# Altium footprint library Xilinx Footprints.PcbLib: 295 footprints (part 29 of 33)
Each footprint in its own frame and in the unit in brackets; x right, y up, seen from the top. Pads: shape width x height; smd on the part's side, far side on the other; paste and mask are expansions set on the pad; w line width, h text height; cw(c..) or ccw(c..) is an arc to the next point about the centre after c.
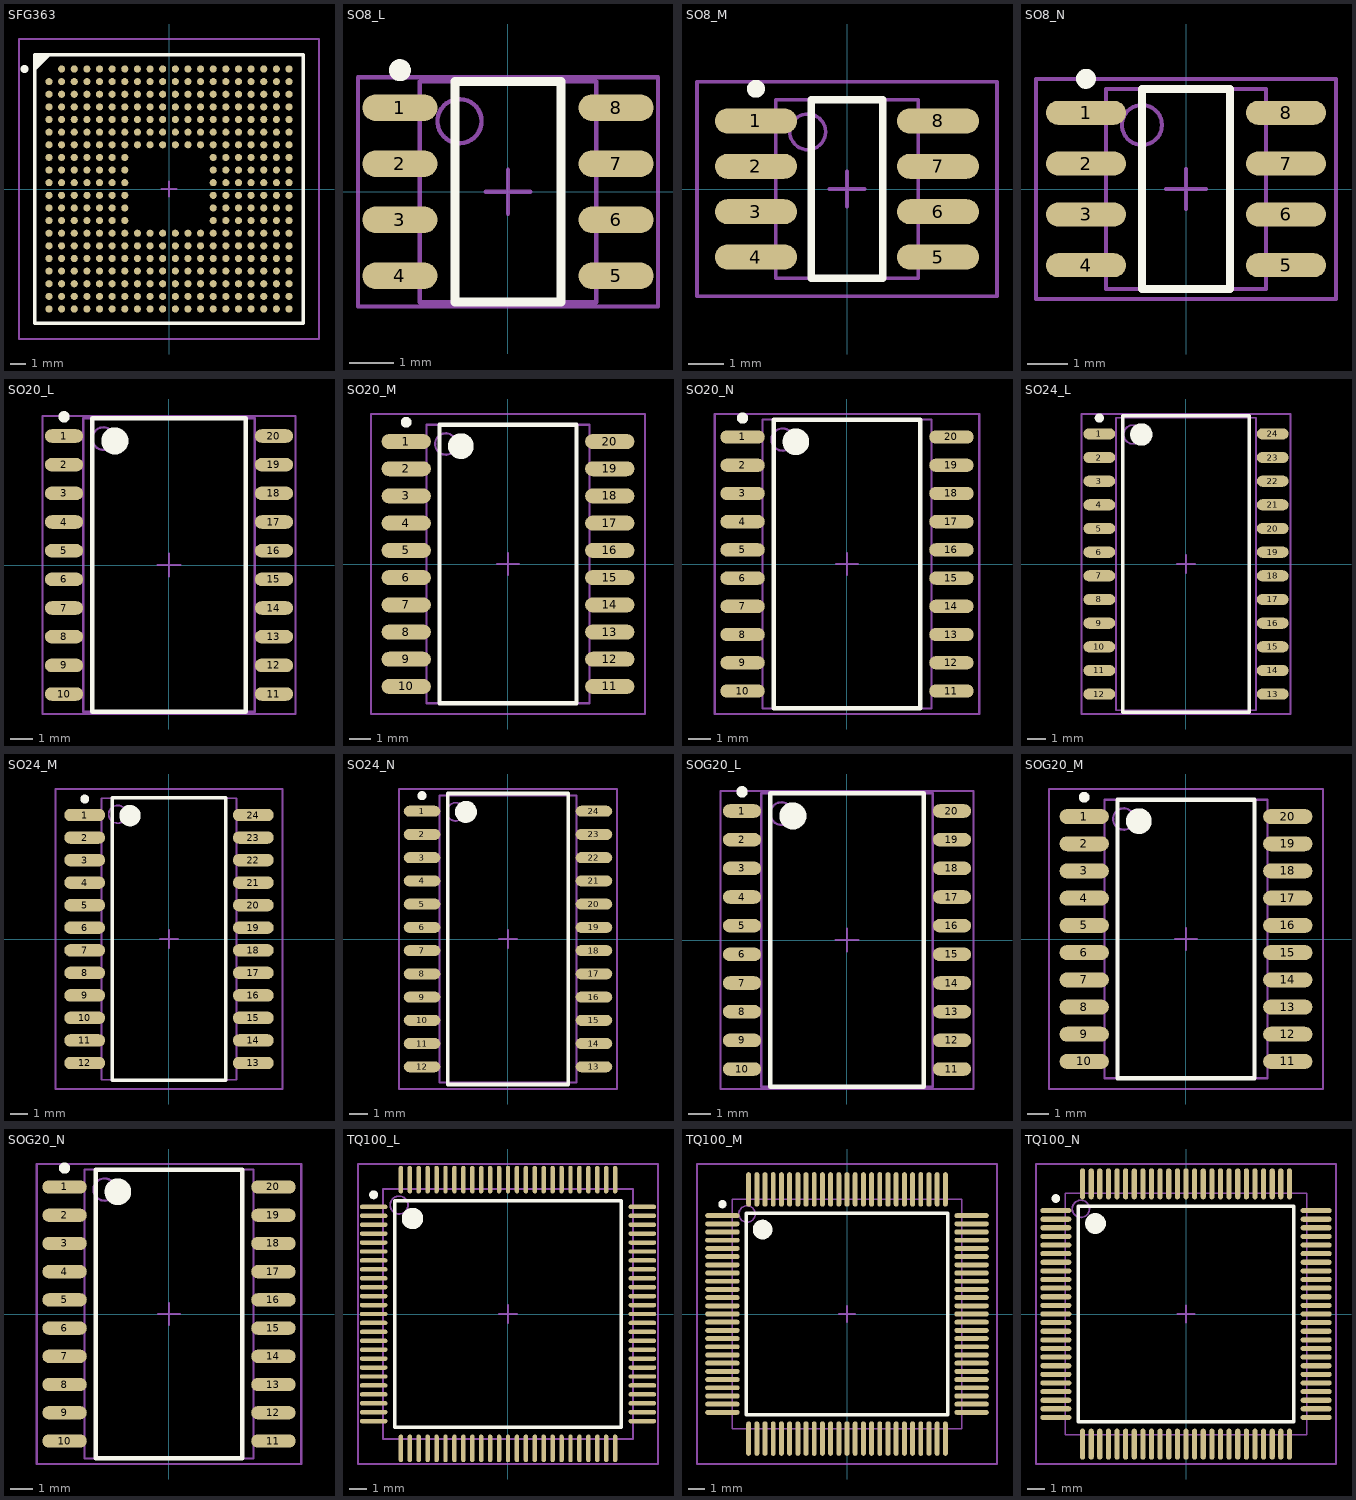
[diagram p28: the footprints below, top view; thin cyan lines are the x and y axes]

## SFG363 [mm] "363-Ball Flip Chip Fine Pitch Ball Grid Array (SFG363) - Pb-Free"
height 1.99
pads (363):
  round 0.45 smd: A2(-6.8,7.6) A3(-6,7.6) A4(-5.2,7.6) A5(-4.4,7.6) A6(-3.6,7.6) A7(-2.8,7.6) A8(-2,7.6) A9(-1.2,7.6) A10(-0.4,7.6) A11(0.4,7.6) A12(1.2,7.6) A13(2,7.6) A14(2.8,7.6) A15(3.6,7.6) A16(4.4,7.6) A17(5.2,7.6) A18(6,7.6) A19(6.8,7.6) A20(7.6,7.6) B1(-7.6,6.8) B2(-6.8,6.8) B3(-6,6.8) B4(-5.2,6.8) B5(-4.4,6.8) B6(-3.6,6.8) B7(-2.8,6.8) B8(-2,6.8) B9(-1.2,6.8) B10(-0.4,6.8) B11(0.4,6.8) B12(1.2,6.8) B13(2,6.8) B14(2.8,6.8) B15(3.6,6.8) B16(4.4,6.8) B17(5.2,6.8) B18(6,6.8) B19(6.8,6.8) B20(7.6,6.8) C1(-7.6,6) C2(-6.8,6) C3(-6,6) C4(-5.2,6) C5(-4.4,6) C6(-3.6,6) C7(-2.8,6) C8(-2,6) C9(-1.2,6) C10(-0.4,6) C11(0.4,6) C12(1.2,6) C13(2,6) C14(2.8,6) C15(3.6,6) C16(4.4,6) C17(5.2,6) C18(6,6) C19(6.8,6) C20(7.6,6) D1(-7.6,5.2) D2(-6.8,5.2) D3(-6,5.2) D4(-5.2,5.2) D5(-4.4,5.2) D6(-3.6,5.2) D7(-2.8,5.2) D8(-2,5.2) D9(-1.2,5.2) D10(-0.4,5.2) D11(0.4,5.2) D12(1.2,5.2) D13(2,5.2) D14(2.8,5.2) D15(3.6,5.2) D16(4.4,5.2) D17(5.2,5.2) D18(6,5.2) D19(6.8,5.2) D20(7.6,5.2) E1(-7.6,4.4) E2(-6.8,4.4) E3(-6,4.4) E4(-5.2,4.4) E5(-4.4,4.4) E6(-3.6,4.4) E7(-2.8,4.4) E8(-2,4.4) E9(-1.2,4.4) E10(-0.4,4.4) E11(0.4,4.4) E12(1.2,4.4) E13(2,4.4) E14(2.8,4.4) E15(3.6,4.4) E16(4.4,4.4) E17(5.2,4.4) E18(6,4.4) E19(6.8,4.4) E20(7.6,4.4) F1(-7.6,3.6) F2(-6.8,3.6) F3(-6,3.6) F4(-5.2,3.6) F5(-4.4,3.6) F6(-3.6,3.6) F7(-2.8,3.6) F8(-2,3.6) F9(-1.2,3.6) F10(-0.4,3.6) F11(0.4,3.6) F12(1.2,3.6) F13(2,3.6) F14(2.8,3.6) F15(3.6,3.6) F16(4.4,3.6) F17(5.2,3.6) F18(6,3.6) F19(6.8,3.6) F20(7.6,3.6) G1(-7.6,2.8) G2(-6.8,2.8) G3(-6,2.8) G4(-5.2,2.8) G5(-4.4,2.8) G6(-3.6,2.8) G7(-2.8,2.8) G8(-2,2.8) G9(-1.2,2.8) G10(-0.4,2.8) G11(0.4,2.8) G12(1.2,2.8) G13(2,2.8) G14(2.8,2.8) G15(3.6,2.8) G16(4.4,2.8) G17(5.2,2.8) G18(6,2.8) G19(6.8,2.8) G20(7.6,2.8) H1(-7.6,2) H2(-6.8,2) H3(-6,2) H4(-5.2,2) H5(-4.4,2) H6(-3.6,2) H7(-2.8,2) H14(2.8,2) H15(3.6,2) H16(4.4,2) H17(5.2,2) H18(6,2) H19(6.8,2) H20(7.6,2) J1(-7.6,1.2) J2(-6.8,1.2) J3(-6,1.2) J4(-5.2,1.2) J5(-4.4,1.2) J6(-3.6,1.2) J7(-2.8,1.2) J14(2.8,1.2) J15(3.6,1.2) J16(4.4,1.2) J17(5.2,1.2) J18(6,1.2) J19(6.8,1.2) J20(7.6,1.2) K1(-7.6,0.4) K2(-6.8,0.4) K3(-6,0.4) K4(-5.2,0.4) K5(-4.4,0.4) K6(-3.6,0.4) K7(-2.8,0.4) K14(2.8,0.4) K15(3.6,0.4) K16(4.4,0.4) K17(5.2,0.4) K18(6,0.4) K19(6.8,0.4) K20(7.6,0.4) L1(-7.6,-0.4) L2(-6.8,-0.4) L3(-6,-0.4) L4(-5.2,-0.4) L5(-4.4,-0.4) L6(-3.6,-0.4) L7(-2.8,-0.4) L14(2.8,-0.4) L15(3.6,-0.4) L16(4.4,-0.4) L17(5.2,-0.4) L18(6,-0.4) L19(6.8,-0.4) L20(7.6,-0.4) M1(-7.6,-1.2) M2(-6.8,-1.2) M3(-6,-1.2) M4(-5.2,-1.2) M5(-4.4,-1.2) M6(-3.6,-1.2) M7(-2.8,-1.2) M14(2.8,-1.2) M15(3.6,-1.2) M16(4.4,-1.2) M17(5.2,-1.2) M18(6,-1.2) M19(6.8,-1.2) M20(7.6,-1.2) N1(-7.6,-2) N2(-6.8,-2) N3(-6,-2) N4(-5.2,-2) N5(-4.4,-2) N6(-3.6,-2) N7(-2.8,-2) N14(2.8,-2) N15(3.6,-2) N16(4.4,-2) N17(5.2,-2) N18(6,-2) N19(6.8,-2) N20(7.6,-2) P1(-7.6,-2.8) P2(-6.8,-2.8) P3(-6,-2.8) P4(-5.2,-2.8) P5(-4.4,-2.8) P6(-3.6,-2.8) P7(-2.8,-2.8) P8(-2,-2.8) P9(-1.2,-2.8) P10(-0.4,-2.8) P11(0.4,-2.8) P12(1.2,-2.8) P13(2,-2.8) P14(2.8,-2.8) P15(3.6,-2.8) P16(4.4,-2.8) P17(5.2,-2.8) P18(6,-2.8) P19(6.8,-2.8) P20(7.6,-2.8) R1(-7.6,-3.6) R2(-6.8,-3.6) R3(-6,-3.6) R4(-5.2,-3.6) R5(-4.4,-3.6) R6(-3.6,-3.6) R7(-2.8,-3.6) R8(-2,-3.6) R9(-1.2,-3.6) R10(-0.4,-3.6) R11(0.4,-3.6) R12(1.2,-3.6) R13(2,-3.6) R14(2.8,-3.6) R15(3.6,-3.6) R16(4.4,-3.6) R17(5.2,-3.6) R18(6,-3.6) R19(6.8,-3.6) R20(7.6,-3.6) T1(-7.6,-4.4) T2(-6.8,-4.4) T3(-6,-4.4) T4(-5.2,-4.4) T5(-4.4,-4.4) T6(-3.6,-4.4) T7(-2.8,-4.4) T8(-2,-4.4) T9(-1.2,-4.4) T10(-0.4,-4.4) T11(0.4,-4.4) T12(1.2,-4.4) T13(2,-4.4) T14(2.8,-4.4) T15(3.6,-4.4) T16(4.4,-4.4) T17(5.2,-4.4) T18(6,-4.4) T19(6.8,-4.4) T20(7.6,-4.4) U1(-7.6,-5.2) U2(-6.8,-5.2) U3(-6,-5.2) U4(-5.2,-5.2) U5(-4.4,-5.2) U6(-3.6,-5.2) U7(-2.8,-5.2) U8(-2,-5.2) U9(-1.2,-5.2) U10(-0.4,-5.2) U11(0.4,-5.2) U12(1.2,-5.2) U13(2,-5.2) U14(2.8,-5.2) U15(3.6,-5.2) U16(4.4,-5.2) U17(5.2,-5.2) U18(6,-5.2) U19(6.8,-5.2) U20(7.6,-5.2) V1(-7.6,-6) V2(-6.8,-6) V3(-6,-6) V4(-5.2,-6) V5(-4.4,-6) V6(-3.6,-6) V7(-2.8,-6) V8(-2,-6) V9(-1.2,-6) V10(-0.4,-6) V11(0.4,-6) V12(1.2,-6) V13(2,-6) V14(2.8,-6) V15(3.6,-6) V16(4.4,-6) V17(5.2,-6) V18(6,-6) V19(6.8,-6) V20(7.6,-6) W1(-7.6,-6.8) W2(-6.8,-6.8) W3(-6,-6.8) W4(-5.2,-6.8) W5(-4.4,-6.8) W6(-3.6,-6.8) W7(-2.8,-6.8) W8(-2,-6.8) W9(-1.2,-6.8) W10(-0.4,-6.8) W11(0.4,-6.8) W12(1.2,-6.8) W13(2,-6.8) W14(2.8,-6.8) W15(3.6,-6.8) W16(4.4,-6.8) W17(5.2,-6.8) W18(6,-6.8) W19(6.8,-6.8) W20(7.6,-6.8) Y1(-7.6,-7.6) Y2(-6.8,-7.6) Y3(-6,-7.6) Y4(-5.2,-7.6) Y5(-4.4,-7.6) Y6(-3.6,-7.6) Y7(-2.8,-7.6) Y8(-2,-7.6) Y9(-1.2,-7.6) Y10(-0.4,-7.6) Y11(0.4,-7.6) Y12(1.2,-7.6) Y13(2,-7.6) Y14(2.8,-7.6) Y15(3.6,-7.6) Y16(4.4,-7.6) Y17(5.2,-7.6) Y18(6,-7.6) Y19(6.8,-7.6) Y20(7.6,-7.6)
Top Overlay:
  circle w0.25: c-9.15,7.6 r0.125
  region: -7.584,8.5 -8.5,7.584 -8.5,8.5
  lines w0.2: -8.5,7.584 -7.584,8.5 ; -8.5,-8.5 8.5,-8.5 8.5,8.5 -8.5,8.5 -8.5,-8.5
Mechanical 13:
  lines w0.1: -8.5,-8.5 8.5,-8.5 8.5,8.5 -8.5,8.5 -8.5,-8.5
Mechanical 15:
  lines w0.1: -0.5,0 0.5,0 ; 0,-0.5 0,0.5 ; -9.5,-9.5 9.5,-9.5 9.5,9.5 -9.5,9.5 -9.5,-9.5
3D body: height 1.99, standoff 0, extent -8.5,-8.5 8.5,8.5

## SO8_L [mm] "8-Pin Small Outline Package (SO8), IPC High Density"
height 1.73
pads (8):
  oval 1.7x0.6 smd: 1(-2.45,1.905) 2(-2.45,0.635) 3(-2.45,-0.635) 4(-2.45,-1.905) 5(2.45,-1.905) 6(2.45,-0.635) 7(2.45,0.635) 8(2.45,1.905)
Top Overlay:
  circle w0.25: c-2.45,2.755 r0.125
  lines w0.2: -1.2,-2.5 1.2,-2.5 1.2,2.5 -1.2,2.5 -1.2,-2.5
Mechanical 13:
  circle w0.1: c-1.1,1.6 r0.5
  lines w0.1: -2,-2.5 2,-2.5 2,2.5 -2,2.5 -2,-2.5
Mechanical 15:
  lines w0.1: -0.5,0 0.5,0 ; 0,-0.5 0,0.5 ; -3.4,-2.6 3.4,-2.6 3.4,2.6 -3.4,2.6 -3.4,-2.6
3D body: height 1.73, standoff 0, extent -2,-2.5 2,2.5

## SO8_M [mm] "8-Pin Small Outline Package (SO8), IPC Low Density"
height 1.73
pads (8):
  oval 2.3x0.7 smd: 1(-2.55,1.905) 2(-2.55,0.635) 3(-2.55,-0.635) 4(-2.55,-1.905) 5(2.55,-1.905) 6(2.55,-0.635) 7(2.55,0.635) 8(2.55,1.905)
Top Overlay:
  circle w0.25: c-2.55,2.805 r0.125
  lines w0.2: -1,-2.5 1,-2.5 1,2.5 -1,2.5 -1,-2.5
Mechanical 13:
  circle w0.1: c-1.1,1.6 r0.5
  lines w0.1: -2,-2.5 2,-2.5 2,2.5 -2,2.5 -2,-2.5
Mechanical 15:
  lines w0.1: -0.5,0 0.5,0 ; 0,-0.5 0,0.5 ; -4.2,-3 4.2,-3 4.2,3 -4.2,3 -4.2,-3
3D body: height 1.73, standoff 0, extent -2,-2.5 2,2.5

## SO8_N [mm] "8-Pin Small Outline Package (SO8), IPC Medium Density"
height 1.73
pads (8):
  oval 2x0.6 smd: 1(-2.5,1.905) 2(-2.5,0.635) 3(-2.5,-0.635) 4(-2.5,-1.905) 5(2.5,-1.905) 6(2.5,-0.635) 7(2.5,0.635) 8(2.5,1.905)
Top Overlay:
  circle w0.25: c-2.5,2.755 r0.125
  lines w0.2: -1.1,-2.5 1.1,-2.5 1.1,2.5 -1.1,2.5 -1.1,-2.5
Mechanical 13:
  circle w0.1: c-1.1,1.6 r0.5
  lines w0.1: -2,-2.5 2,-2.5 2,2.5 -2,2.5 -2,-2.5
Mechanical 15:
  lines w0.1: -0.5,0 0.5,0 ; 0,-0.5 0,0.5 ; -3.75,-2.75 3.75,-2.75 3.75,2.75 -3.75,2.75 -3.75,-2.75
3D body: height 1.73, standoff 0, extent -2,-2.5 2,2.5

## SO20_L [mm] "20-Pin Small Outline Package (SO20), IPC High Density"
height 2.65
pads (20):
  oval 1.7x0.6 smd: 1(-4.65,5.715) 2(-4.65,4.445) 3(-4.65,3.175) 4(-4.65,1.905) 5(-4.65,0.635) 6(-4.65,-0.635) 7(-4.65,-1.905) 8(-4.65,-3.175) 9(-4.65,-4.445) 10(-4.65,-5.715) 11(4.65,-5.715) 12(4.65,-4.445) 13(4.65,-3.175) 14(4.65,-1.905) 15(4.65,-0.635) 16(4.65,0.635) 17(4.65,1.905) 18(4.65,3.175) 19(4.65,4.445) 20(4.65,5.715)
Top Overlay:
  circle w0.25: c-4.65,6.565 r0.125
  circle w0.6: c-2.4,5.5 r0.3
  lines w0.2: -3.4,-6.5 -3.4,6.5 3.4,6.5 3.4,-6.5 -3.4,-6.5
Mechanical 13:
  circle w0.1: c-2.9,5.6 r0.5
  lines w0.1: -3.8,-6.5 -3.8,6.5 3.8,6.5 3.8,-6.5 -3.8,-6.5
Mechanical 15:
  lines w0.1: -0.5,0 0.5,0 ; 0,-0.5 0,0.5 ; -5.6,-6.6 -5.6,6.6 5.6,6.6 5.6,-6.6 -5.6,-6.6
3D body: height 2.65, standoff 0, extent -3.8,-6.5 3.8,6.5

## SO20_M [mm] "20-Pin Small Outline Package (SO20), IPC Low Density"
height 2.65
pads (20):
  oval 2.3x0.7 smd: 1(-4.75,5.715) 2(-4.75,4.445) 3(-4.75,3.175) 4(-4.75,1.905) 5(-4.75,0.635) 6(-4.75,-0.635) 7(-4.75,-1.905) 8(-4.75,-3.175) 9(-4.75,-4.445) 10(-4.75,-5.715) 11(4.75,-5.715) 12(4.75,-4.445) 13(4.75,-3.175) 14(4.75,-1.905) 15(4.75,-0.635) 16(4.75,0.635) 17(4.75,1.905) 18(4.75,3.175) 19(4.75,4.445) 20(4.75,5.715)
Top Overlay:
  circle w0.25: c-4.75,6.615 r0.125
  circle w0.6: c-2.2,5.5 r0.3
  lines w0.2: -3.2,-6.5 -3.2,6.5 3.2,6.5 3.2,-6.5 -3.2,-6.5
Mechanical 13:
  circle w0.1: c-2.9,5.6 r0.5
  lines w0.1: -3.8,-6.5 -3.8,6.5 3.8,6.5 3.8,-6.5 -3.8,-6.5
Mechanical 15:
  lines w0.1: -0.5,0 0.5,0 ; 0,-0.5 0,0.5 ; -6.4,-7 -6.4,7 6.4,7 6.4,-7 -6.4,-7
3D body: height 2.65, standoff 0, extent -3.8,-6.5 3.8,6.5

## SO20_N [mm] "20-Pin Small Outline Package (SO20), IPC Medium Density"
height 2.65
pads (20):
  oval 2x0.6 smd: 1(-4.7,5.715) 2(-4.7,4.445) 3(-4.7,3.175) 4(-4.7,1.905) 5(-4.7,0.635) 6(-4.7,-0.635) 7(-4.7,-1.905) 8(-4.7,-3.175) 9(-4.7,-4.445) 10(-4.7,-5.715) 11(4.7,-5.715) 12(4.7,-4.445) 13(4.7,-3.175) 14(4.7,-1.905) 15(4.7,-0.635) 16(4.7,0.635) 17(4.7,1.905) 18(4.7,3.175) 19(4.7,4.445) 20(4.7,5.715)
Top Overlay:
  circle w0.25: c-4.7,6.565 r0.125
  circle w0.6: c-2.3,5.5 r0.3
  lines w0.2: -3.3,-6.5 -3.3,6.5 3.3,6.5 3.3,-6.5 -3.3,-6.5
Mechanical 13:
  circle w0.1: c-2.9,5.6 r0.5
  lines w0.1: -3.8,-6.5 -3.8,6.5 3.8,6.5 3.8,-6.5 -3.8,-6.5
Mechanical 15:
  lines w0.1: -0.5,0 0.5,0 ; 0,-0.5 0,0.5 ; -5.95,-6.75 -5.95,6.75 5.95,6.75 5.95,-6.75 -5.95,-6.75
3D body: height 2.65, standoff 0, extent -3.8,-6.5 3.8,6.5

## SO24_L [mm] "24-Pin Small Outline Package (SO24), IPC High Density"
height 2.65
pads (24):
  oval 1.7x0.6 smd: 1(-4.65,6.985) 2(-4.65,5.715) 3(-4.65,4.445) 4(-4.65,3.175) 5(-4.65,1.905) 6(-4.65,0.635) 7(-4.65,-0.635) 8(-4.65,-1.905) 9(-4.65,-3.175) 10(-4.65,-4.445) 11(-4.65,-5.715) 12(-4.65,-6.985) 13(4.65,-6.985) 14(4.65,-5.715) 15(4.65,-4.445) 16(4.65,-3.175) 17(4.65,-1.905) 18(4.65,-0.635) 19(4.65,0.635) 20(4.65,1.905) 21(4.65,3.175) 22(4.65,4.445) 23(4.65,5.715) 24(4.65,6.985)
Top Overlay:
  circle w0.25: c-4.65,7.835 r0.125
  circle w0.6: c-2.4,6.95 r0.3
  lines w0.2: -3.4,-7.95 -3.4,7.95 3.4,7.95 3.4,-7.95 -3.4,-7.95
Mechanical 13:
  circle w0.1: c-2.85,6.95 r0.5
  lines w0.1: -3.75,-7.85 -3.75,7.85 3.75,7.85 3.75,-7.85 -3.75,-7.85
Mechanical 15:
  lines w0.1: -0.5,0 0.5,0 ; 0,-0.5 0,0.5 ; -5.6,-8.05 -5.6,8.05 5.6,8.05 5.6,-8.05 -5.6,-8.05
3D body: height 2.65, standoff 0, extent -3.75,-7.85 3.75,7.85

## SO24_M [mm] "24-Pin Small Outline Package (SO24), IPC Low Density"
height 2.65
pads (24):
  oval 2.3x0.7 smd: 1(-4.75,6.985) 2(-4.75,5.715) 3(-4.75,4.445) 4(-4.75,3.175) 5(-4.75,1.905) 6(-4.75,0.635) 7(-4.75,-0.635) 8(-4.75,-1.905) 9(-4.75,-3.175) 10(-4.75,-4.445) 11(-4.75,-5.715) 12(-4.75,-6.985) 13(4.75,-6.985) 14(4.75,-5.715) 15(4.75,-4.445) 16(4.75,-3.175) 17(4.75,-1.905) 18(4.75,-0.635) 19(4.75,0.635) 20(4.75,1.905) 21(4.75,3.175) 22(4.75,4.445) 23(4.75,5.715) 24(4.75,6.985)
Top Overlay:
  circle w0.25: c-4.75,7.885 r0.125
  circle w0.6: c-2.2,6.95 r0.3
  lines w0.2: -3.2,-7.95 -3.2,7.95 3.2,7.95 3.2,-7.95 -3.2,-7.95
Mechanical 13:
  circle w0.1: c-2.9,7.025 r0.5
  lines w0.1: -3.8,-7.925 -3.8,7.925 3.8,7.925 3.8,-7.925 -3.8,-7.925
Mechanical 15:
  lines w0.1: -0.5,0 0.5,0 ; 0,-0.5 0,0.5 ; -6.4,-8.45 -6.4,8.45 6.4,8.45 6.4,-8.45 -6.4,-8.45
3D body: height 2.65, standoff 0, extent -3.8,-7.925 3.8,7.925

## SO24_N [mm] "24-Pin Small Outline Package (SO24), IPC Medium Density"
height 2.65
pads (24):
  oval 2x0.6 smd: 1(-4.7,6.985) 2(-4.7,5.715) 3(-4.7,4.445) 4(-4.7,3.175) 5(-4.7,1.905) 6(-4.7,0.635) 7(-4.7,-0.635) 8(-4.7,-1.905) 9(-4.7,-3.175) 10(-4.7,-4.445) 11(-4.7,-5.715) 12(-4.7,-6.985) 13(4.7,-6.985) 14(4.7,-5.715) 15(4.7,-4.445) 16(4.7,-3.175) 17(4.7,-1.905) 18(4.7,-0.635) 19(4.7,0.635) 20(4.7,1.905) 21(4.7,3.175) 22(4.7,4.445) 23(4.7,5.715) 24(4.7,6.985)
Top Overlay:
  circle w0.25: c-4.7,7.835 r0.125
  circle w0.6: c-2.3,6.95 r0.3
  lines w0.2: -3.3,-7.95 -3.3,7.95 3.3,7.95 3.3,-7.95 -3.3,-7.95
Mechanical 13:
  circle w0.1: c-2.85,6.95 r0.5
  lines w0.1: -3.75,-7.85 -3.75,7.85 3.75,7.85 3.75,-7.85 -3.75,-7.85
Mechanical 15:
  lines w0.1: -0.5,0 0.5,0 ; 0,-0.5 0,0.5 ; -5.95,-8.2 -5.95,8.2 5.95,8.2 5.95,-8.2 -5.95,-8.2
3D body: height 2.65, standoff 0, extent -3.75,-7.85 3.75,7.85

## SOG20_L [mm] "20-Pin Small Outline Package (SOG20) - Pb-Free, IPC High Density"
height 2.65
pads (20):
  oval 1.7x0.6 smd: 1(-4.65,5.715) 2(-4.65,4.445) 3(-4.65,3.175) 4(-4.65,1.905) 5(-4.65,0.635) 6(-4.65,-0.635) 7(-4.65,-1.905) 8(-4.65,-3.175) 9(-4.65,-4.445) 10(-4.65,-5.715) 11(4.65,-5.715) 12(4.65,-4.445) 13(4.65,-3.175) 14(4.65,-1.905) 15(4.65,-0.635) 16(4.65,0.635) 17(4.65,1.905) 18(4.65,3.175) 19(4.65,4.445) 20(4.65,5.715)
Top Overlay:
  circle w0.25: c-4.65,6.565 r0.125
  circle w0.6: c-2.4,5.5 r0.3
  lines w0.2: -3.4,-6.5 -3.4,6.5 3.4,6.5 3.4,-6.5 -3.4,-6.5
Mechanical 13:
  circle w0.1: c-2.9,5.6 r0.5
  lines w0.1: -3.8,-6.5 -3.8,6.5 3.8,6.5 3.8,-6.5 -3.8,-6.5
Mechanical 15:
  lines w0.1: -0.5,0 0.5,0 ; 0,-0.5 0,0.5 ; -5.6,-6.6 -5.6,6.6 5.6,6.6 5.6,-6.6 -5.6,-6.6
3D body: height 2.65, standoff 0, extent -3.8,-6.5 3.8,6.5

## SOG20_M [mm] "20-Pin Small Outline Package (SOG20) - Pb-Free, IPC Low Density"
height 2.65
pads (20):
  oval 2.3x0.7 smd: 1(-4.75,5.715) 2(-4.75,4.445) 3(-4.75,3.175) 4(-4.75,1.905) 5(-4.75,0.635) 6(-4.75,-0.635) 7(-4.75,-1.905) 8(-4.75,-3.175) 9(-4.75,-4.445) 10(-4.75,-5.715) 11(4.75,-5.715) 12(4.75,-4.445) 13(4.75,-3.175) 14(4.75,-1.905) 15(4.75,-0.635) 16(4.75,0.635) 17(4.75,1.905) 18(4.75,3.175) 19(4.75,4.445) 20(4.75,5.715)
Top Overlay:
  circle w0.25: c-4.75,6.615 r0.125
  circle w0.6: c-2.2,5.5 r0.3
  lines w0.2: -3.2,-6.5 -3.2,6.5 3.2,6.5 3.2,-6.5 -3.2,-6.5
Mechanical 13:
  circle w0.1: c-2.9,5.6 r0.5
  lines w0.1: -3.8,-6.5 -3.8,6.5 3.8,6.5 3.8,-6.5 -3.8,-6.5
Mechanical 15:
  lines w0.1: -0.5,0 0.5,0 ; 0,-0.5 0,0.5 ; -6.4,-7 -6.4,7 6.4,7 6.4,-7 -6.4,-7
3D body: height 2.65, standoff 0, extent -3.8,-6.5 3.8,6.5

## SOG20_N [mm] "20-Pin Small Outline Package (SOG20) - Pb-Free, IPC Medium Density"
height 2.65
pads (20):
  oval 2x0.6 smd: 1(-4.7,5.715) 2(-4.7,4.445) 3(-4.7,3.175) 4(-4.7,1.905) 5(-4.7,0.635) 6(-4.7,-0.635) 7(-4.7,-1.905) 8(-4.7,-3.175) 9(-4.7,-4.445) 10(-4.7,-5.715) 11(4.7,-5.715) 12(4.7,-4.445) 13(4.7,-3.175) 14(4.7,-1.905) 15(4.7,-0.635) 16(4.7,0.635) 17(4.7,1.905) 18(4.7,3.175) 19(4.7,4.445) 20(4.7,5.715)
Top Overlay:
  circle w0.25: c-4.7,6.565 r0.125
  circle w0.6: c-2.3,5.5 r0.3
  lines w0.2: -3.3,-6.5 -3.3,6.5 3.3,6.5 3.3,-6.5 -3.3,-6.5
Mechanical 13:
  circle w0.1: c-2.9,5.6 r0.5
  lines w0.1: -3.8,-6.5 -3.8,6.5 3.8,6.5 3.8,-6.5 -3.8,-6.5
Mechanical 15:
  lines w0.1: -0.5,0 0.5,0 ; 0,-0.5 0,0.5 ; -5.95,-6.75 -5.95,6.75 5.95,6.75 5.95,-6.75 -5.95,-6.75
3D body: height 2.65, standoff 0, extent -3.8,-6.5 3.8,6.5

## TQ100_L [mm] "100-Pin Thin Quad Flat Pack (TQ100), IPC High Density"
height 1.6
pads (100):
  oval 1.55x0.25 smd: 1(-7.525,6) 2(-7.525,5.5) 3(-7.525,5) 4(-7.525,4.5) 5(-7.525,4) 6(-7.525,3.5) 7(-7.525,3) 8(-7.525,2.5) 9(-7.525,2) 10(-7.525,1.5) 11(-7.525,1) 12(-7.525,0.5) 13(-7.525,0) 14(-7.525,-0.5) 15(-7.525,-1) 16(-7.525,-1.5) 17(-7.525,-2) 18(-7.525,-2.5) 19(-7.525,-3) 20(-7.525,-3.5) 21(-7.525,-4) 22(-7.525,-4.5) 23(-7.525,-5) 24(-7.525,-5.5) 25(-7.525,-6) 51(7.525,-6) 52(7.525,-5.5) 53(7.525,-5) 54(7.525,-4.5) 55(7.525,-4) 56(7.525,-3.5) 57(7.525,-3) 58(7.525,-2.5) 59(7.525,-2) 60(7.525,-1.5) 61(7.525,-1) 62(7.525,-0.5) 63(7.525,0) 64(7.525,0.5) 65(7.525,1) 66(7.525,1.5) 67(7.525,2) 68(7.525,2.5) 69(7.525,3) 70(7.525,3.5) 71(7.525,4) 72(7.525,4.5) 73(7.525,5) 74(7.525,5.5) 75(7.525,6)
  oval 0.25x1.55 smd: 26(-6,-7.525) 27(-5.5,-7.525) 28(-5,-7.525) 29(-4.5,-7.525) 30(-4,-7.525) 31(-3.5,-7.525) 32(-3,-7.525) 33(-2.5,-7.525) 34(-2,-7.525) 35(-1.5,-7.525) 36(-1,-7.525) 37(-0.5,-7.525) 38(0,-7.525) 39(0.5,-7.525) 40(1,-7.525) 41(1.5,-7.525) 42(2,-7.525) 43(2.5,-7.525) 44(3,-7.525) 45(3.5,-7.525) 46(4,-7.525) 47(4.5,-7.525) 48(5,-7.525) 49(5.5,-7.525) 50(6,-7.525) 76(6,7.525) 77(5.5,7.525) 78(5,7.525) 79(4.5,7.525) 80(4,7.525) 81(3.5,7.525) 82(3,7.525) 83(2.5,7.525) 84(2,7.525) 85(1.5,7.525) 86(1,7.525) 87(0.5,7.525) 88(0,7.525) 89(-0.5,7.525) 90(-1,7.525) 91(-1.5,7.525) 92(-2,7.525) 93(-2.5,7.525) 94(-3,7.525) 95(-3.5,7.525) 96(-4,7.525) 97(-4.5,7.525) 98(-5,7.525) 99(-5.5,7.525) 100(-6,7.525)
Top Overlay:
  circle w0.25: c-7.525,6.675 r0.125
  circle w0.6: c-5.35,5.35 r0.3
  lines w0.2: -6.35,-6.35 -6.35,6.35 6.35,6.35 6.35,-6.35 -6.35,-6.35
Mechanical 13:
  circle w0.1: c-6.1,6.1 r0.5
  lines w0.1: -7,-7 -7,7 7,7 7,-7 -7,-7
Mechanical 15:
  lines w0.1: -0.5,0 0.5,0 ; 0,-0.5 0,0.5 ; -8.4,-8.4 -8.4,8.4 8.4,8.4 8.4,-8.4 -8.4,-8.4
3D body: height 1.6, standoff 0, extent -7,-7 7,7

## TQ100_M [mm] "100-Pin Thin Quad Flat Pack (TQ100), IPC Low Density"
height 1.6
pads (100):
  oval 2.1x0.3 smd: 1(-7.6,6) 2(-7.6,5.5) 3(-7.6,5) 4(-7.6,4.5) 5(-7.6,4) 6(-7.6,3.5) 7(-7.6,3) 8(-7.6,2.5) 9(-7.6,2) 10(-7.6,1.5) 11(-7.6,1) 12(-7.6,0.5) 13(-7.6,0) 14(-7.6,-0.5) 15(-7.6,-1) 16(-7.6,-1.5) 17(-7.6,-2) 18(-7.6,-2.5) 19(-7.6,-3) 20(-7.6,-3.5) 21(-7.6,-4) 22(-7.6,-4.5) 23(-7.6,-5) 24(-7.6,-5.5) 25(-7.6,-6) 51(7.6,-6) 52(7.6,-5.5) 53(7.6,-5) 54(7.6,-4.5) 55(7.6,-4) 56(7.6,-3.5) 57(7.6,-3) 58(7.6,-2.5) 59(7.6,-2) 60(7.6,-1.5) 61(7.6,-1) 62(7.6,-0.5) 63(7.6,0) 64(7.6,0.5) 65(7.6,1) 66(7.6,1.5) 67(7.6,2) 68(7.6,2.5) 69(7.6,3) 70(7.6,3.5) 71(7.6,4) 72(7.6,4.5) 73(7.6,5) 74(7.6,5.5) 75(7.6,6)
  oval 0.3x2.1 smd: 26(-6,-7.6) 27(-5.5,-7.6) 28(-5,-7.6) 29(-4.5,-7.6) 30(-4,-7.6) 31(-3.5,-7.6) 32(-3,-7.6) 33(-2.5,-7.6) 34(-2,-7.6) 35(-1.5,-7.6) 36(-1,-7.6) 37(-0.5,-7.6) 38(0,-7.6) 39(0.5,-7.6) 40(1,-7.6) 41(1.5,-7.6) 42(2,-7.6) 43(2.5,-7.6) 44(3,-7.6) 45(3.5,-7.6) 46(4,-7.6) 47(4.5,-7.6) 48(5,-7.6) 49(5.5,-7.6) 50(6,-7.6) 76(6,7.6) 77(5.5,7.6) 78(5,7.6) 79(4.5,7.6) 80(4,7.6) 81(3.5,7.6) 82(3,7.6) 83(2.5,7.6) 84(2,7.6) 85(1.5,7.6) 86(1,7.6) 87(0.5,7.6) 88(0,7.6) 89(-0.5,7.6) 90(-1,7.6) 91(-1.5,7.6) 92(-2,7.6) 93(-2.5,7.6) 94(-3,7.6) 95(-3.5,7.6) 96(-4,7.6) 97(-4.5,7.6) 98(-5,7.6) 99(-5.5,7.6) 100(-6,7.6)
Top Overlay:
  circle w0.6: c-5.15,5.15 r0.3
  circle w0.25: c-7.6,6.7 r0.125
  lines w0.2: -6.15,-6.15 6.15,-6.15 6.15,6.15 -6.15,6.15 -6.15,-6.15
Mechanical 13:
  circle w0.1: c-6.1,6.1 r0.5
  lines w0.1: -7,-7 7,-7 7,7 -7,7 -7,-7
Mechanical 15:
  lines w0.1: -0.5,0 0.5,0 ; 0,-0.5 0,0.5 ; -9.15,-9.15 9.15,-9.15 9.15,9.15 -9.15,9.15 -9.15,-9.15
3D body: height 1.6, standoff 0, extent -7,-7 7,7

## TQ100_N [mm] "100-Pin Thin Quad Flat Pack (TQ100), IPC Medium Density"
height 1.6
pads (100):
  oval 1.8x0.3 smd: 1(-7.55,6) 2(-7.55,5.5) 3(-7.55,5) 4(-7.55,4.5) 5(-7.55,4) 6(-7.55,3.5) 7(-7.55,3) 8(-7.55,2.5) 9(-7.55,2) 10(-7.55,1.5) 11(-7.55,1) 12(-7.55,0.5) 13(-7.55,0) 14(-7.55,-0.5) 15(-7.55,-1) 16(-7.55,-1.5) 17(-7.55,-2) 18(-7.55,-2.5) 19(-7.55,-3) 20(-7.55,-3.5) 21(-7.55,-4) 22(-7.55,-4.5) 23(-7.55,-5) 24(-7.55,-5.5) 25(-7.55,-6) 51(7.55,-6) 52(7.55,-5.5) 53(7.55,-5) 54(7.55,-4.5) 55(7.55,-4) 56(7.55,-3.5) 57(7.55,-3) 58(7.55,-2.5) 59(7.55,-2) 60(7.55,-1.5) 61(7.55,-1) 62(7.55,-0.5) 63(7.55,0) 64(7.55,0.5) 65(7.55,1) 66(7.55,1.5) 67(7.55,2) 68(7.55,2.5) 69(7.55,3) 70(7.55,3.5) 71(7.55,4) 72(7.55,4.5) 73(7.55,5) 74(7.55,5.5) 75(7.55,6)
  oval 0.3x1.8 smd: 26(-6,-7.55) 27(-5.5,-7.55) 28(-5,-7.55) 29(-4.5,-7.55) 30(-4,-7.55) 31(-3.5,-7.55) 32(-3,-7.55) 33(-2.5,-7.55) 34(-2,-7.55) 35(-1.5,-7.55) 36(-1,-7.55) 37(-0.5,-7.55) 38(0,-7.55) 39(0.5,-7.55) 40(1,-7.55) 41(1.5,-7.55) 42(2,-7.55) 43(2.5,-7.55) 44(3,-7.55) 45(3.5,-7.55) 46(4,-7.55) 47(4.5,-7.55) 48(5,-7.55) 49(5.5,-7.55) 50(6,-7.55) 76(6,7.55) 77(5.5,7.55) 78(5,7.55) 79(4.5,7.55) 80(4,7.55) 81(3.5,7.55) 82(3,7.55) 83(2.5,7.55) 84(2,7.55) 85(1.5,7.55) 86(1,7.55) 87(0.5,7.55) 88(0,7.55) 89(-0.5,7.55) 90(-1,7.55) 91(-1.5,7.55) 92(-2,7.55) 93(-2.5,7.55) 94(-3,7.55) 95(-3.5,7.55) 96(-4,7.55) 97(-4.5,7.55) 98(-5,7.55) 99(-5.5,7.55) 100(-6,7.55)
Top Overlay:
  circle w0.6: c-5.25,5.25 r0.3
  circle w0.25: c-7.55,6.7 r0.125
  lines w0.2: -6.25,-6.25 6.25,-6.25 6.25,6.25 -6.25,6.25 -6.25,-6.25
Mechanical 13:
  circle w0.1: c-6.1,6.1 r0.5
  lines w0.1: -7,-7 7,-7 7,7 -7,7 -7,-7
Mechanical 15:
  lines w0.1: -0.5,0 0.5,0 ; 0,-0.5 0,0.5 ; -8.7,-8.7 8.7,-8.7 8.7,8.7 -8.7,8.7 -8.7,-8.7
3D body: height 1.6, standoff 0, extent -7,-7 7,7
